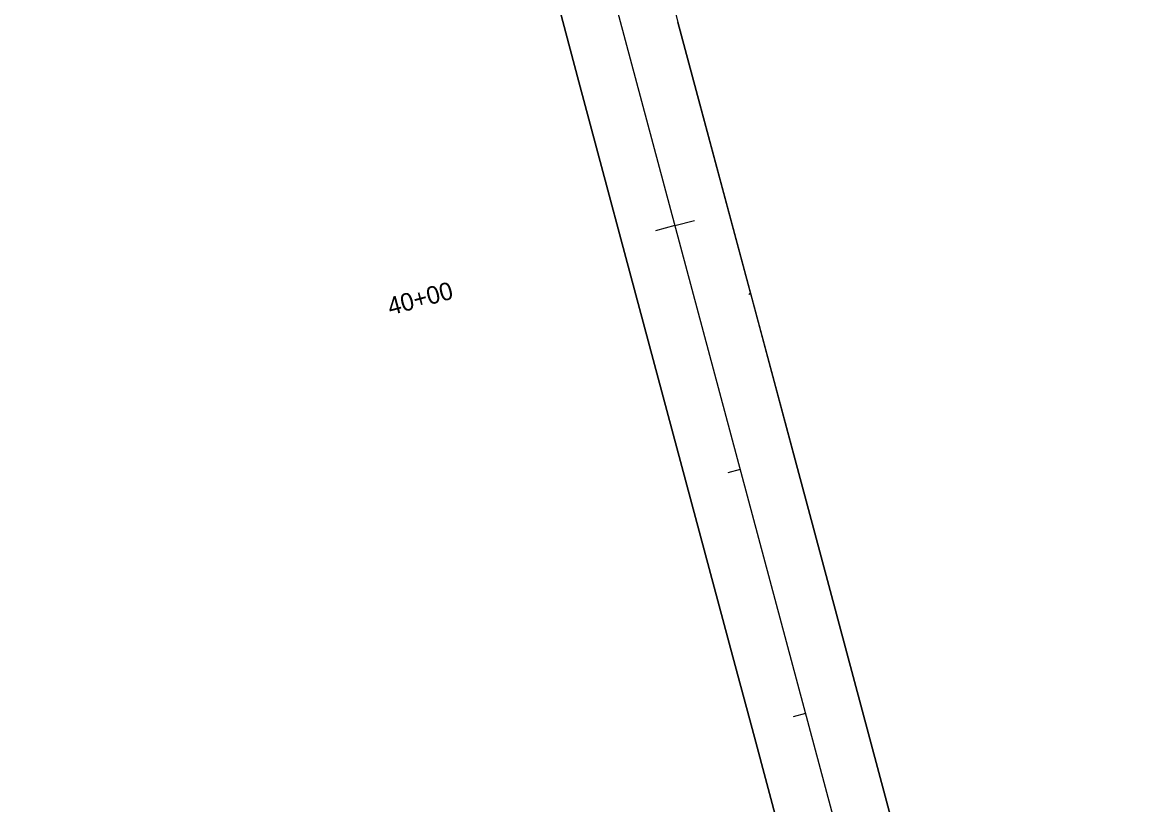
# Model space of a CAD drawing. Extents: x 1616561 to 1622460, y 896726 to 899651.
# Drawn here: x 1621287.6 to 1621727.5, y 897725.7 to 898035.6 of the extents above; entities that cross this region are included whole.
import ezdxf

# ---------------------------------------------------------------- set-up
doc = ezdxf.new("R2010")
doc.units = 0
for name, color, linetype in [('Old_Level_40', 7, 'Continuous'), ('Prop Dimension', 7, 'Continuous'), ('Prop Horizontal Alignment', 7, 'Continuous'), ('Prop Shade Light', 7, 'Continuous'), ('Prop Superelevation  Arrow CELL', 7, 'Continuous'), ('Prop Superelevation Label', 7, 'Continuous'), ('Sheet Cutting Line CELL', 7, 'Continuous')]:
    doc.layers.add(name, color=color, linetype=linetype)

msp = doc.modelspace()

# ---------------------------------------------------------------- linework, layer by layer
at = {"layer": 'Old_Level_40'}
for p, q in [((1621534.52, 898083.44), (1621547.33, 898035.56)), ((1621502.92, 898031.33), (1621492.01, 898072.07)), ((1621547.33, 898035.56), (1621554.57, 898008.51)), ((1621508.09, 898012.01), (1621502.92, 898031.33)), ((1621519.58, 897969.09), (1621508.09, 898012.01)), ((1621554.57, 898008.51), (1621593.72, 897862.28)), ((1621524.75, 897949.77), (1621519.58, 897969.09)), ((1621569.06, 897784.24), (1621524.75, 897949.77)), ((1621593.72, 897862.28), (1621600.95, 897835.24)), ((1621600.95, 897835.24), (1621682.63, 897530.11)), ((1621577.58, 897752.39), (1621569.06, 897784.24)), ((1621607.85, 897639.29), (1621577.58, 897752.39))]:
    msp.add_line(p, q, dxfattribs=at)
at = {"layer": 'Prop Horizontal Alignment'}
for p, q in [((1621492.01, 898072.07), (1621502.92, 898031.33)), ((1621508.09, 898012.01), (1621519.58, 897969.09)), ((1621554.57, 898008.51), (1621593.72, 897862.28)), ((1621524.75, 897949.77), (1621569.06, 897784.24)), ((1621600.95, 897835.24), (1621682.63, 897530.11)), ((1621577.58, 897752.39), (1621607.85, 897639.29))]:
    msp.add_line(p, q, dxfattribs=at)
at = {"layer": 'Prop Shade Light'}
for p, q in [((1621492.01, 898072.07), (1621502.92, 898031.33)), ((1621554.57, 898008.51), (1621547.33, 898035.56)), ((1621502.92, 898031.33), (1621508.09, 898012.01)), ((1621508.09, 898012.01), (1621519.58, 897969.09)), ((1621576.03, 897928.36), (1621554.57, 898008.51)), ((1621519.58, 897969.09), (1621524.75, 897949.77)), ((1621524.75, 897949.77), (1621569.06, 897784.24)), ((1621575.37, 897927.79), (1621576.03, 897928.36)), ((1621593.72, 897862.28), (1621576.13, 897927.99)), ((1621600.95, 897835.24), (1621593.72, 897862.28)), ((1621682.63, 897530.11), (1621600.95, 897835.24)), ((1621569.06, 897784.24), (1621577.58, 897752.39)), ((1621577.58, 897752.39), (1621607.85, 897639.29))]:
    msp.add_line(p, q, dxfattribs=at)
msp.add_lwpolyline([(1621576.13, 897927.99), (1621575.37, 897927.79)], dxfattribs=at)
at = {"layer": 'Prop Superelevation  Arrow CELL'}
for p, q in [((1621571.97, 897858.42), (1621567.14, 897857.13)), ((1621597.83, 897761.82), (1621593, 897760.53))]:
    msp.add_line(p, q, dxfattribs=at)
at = {"layer": 'Prop Superelevation Label'}
for q in [(1621553.84, 897957.09), (1621538.39, 897952.95)]:
    msp.add_line((1621546.12, 897955.02), q, dxfattribs=at)
at = {"layer": 'Sheet Cutting Line CELL'}
msp.add_line((1621287.55, 898921.02), (1621727.49, 897277.4), dxfattribs=at)

# ---------------------------------------------------------------- texts
at = {"layer": 'Prop Dimension'}
msp.add_text('40+00', height=7, rotation=14.985, dxfattribs=at).set_placement((1621433.39, 897919.42))

doc.saveas('drawing.dxf')
